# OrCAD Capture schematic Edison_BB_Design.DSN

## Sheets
1 02) Table of Contents: title: TABLE OF CONTENTS; rev: 2; note: H49905
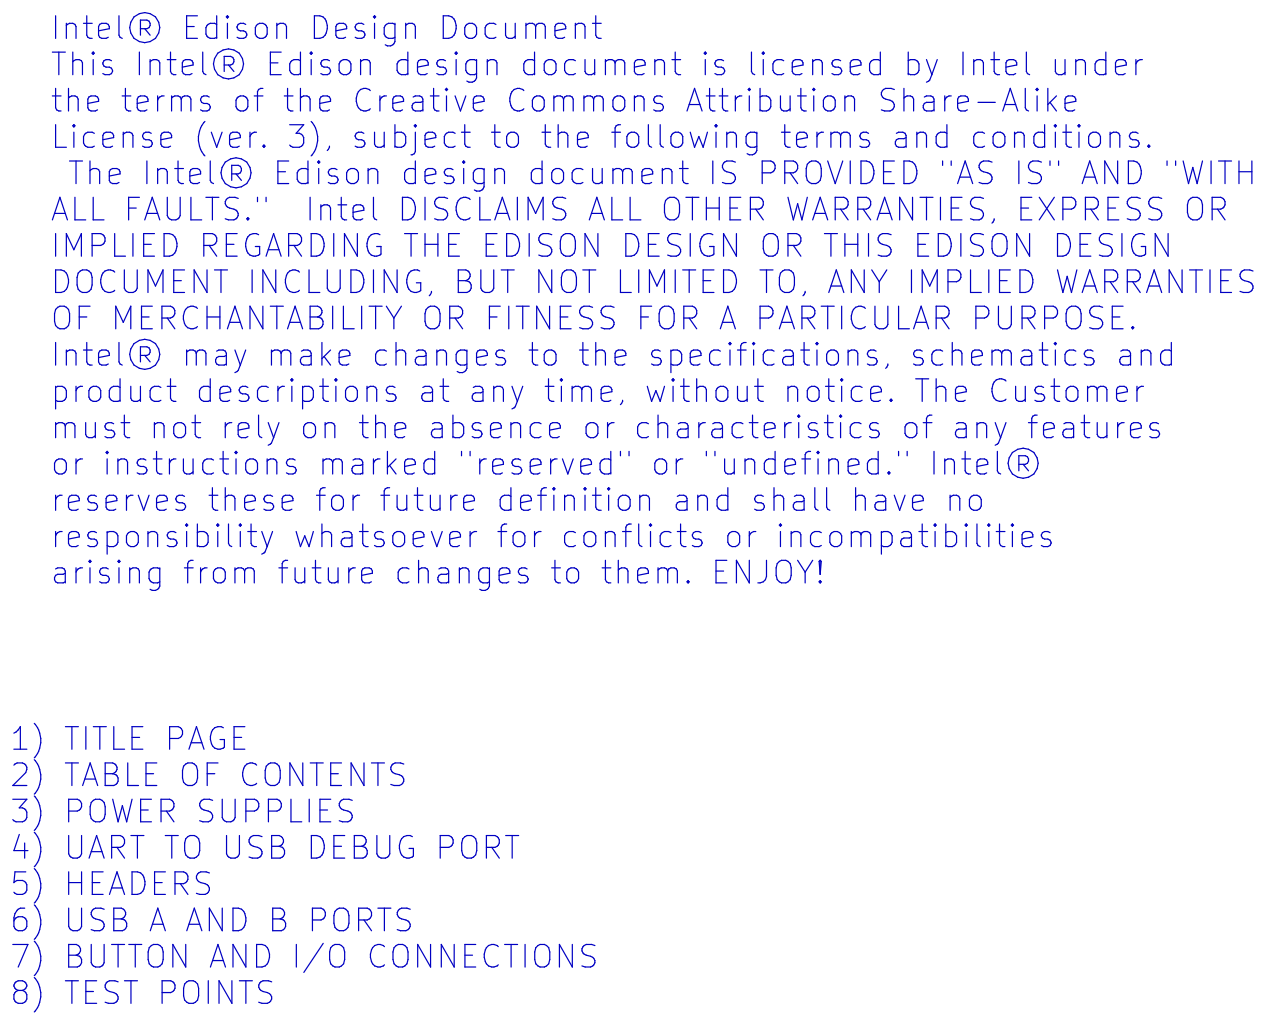
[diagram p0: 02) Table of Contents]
2 03) POWER SUPPLIES: size A; title: POWER SUPPLIES
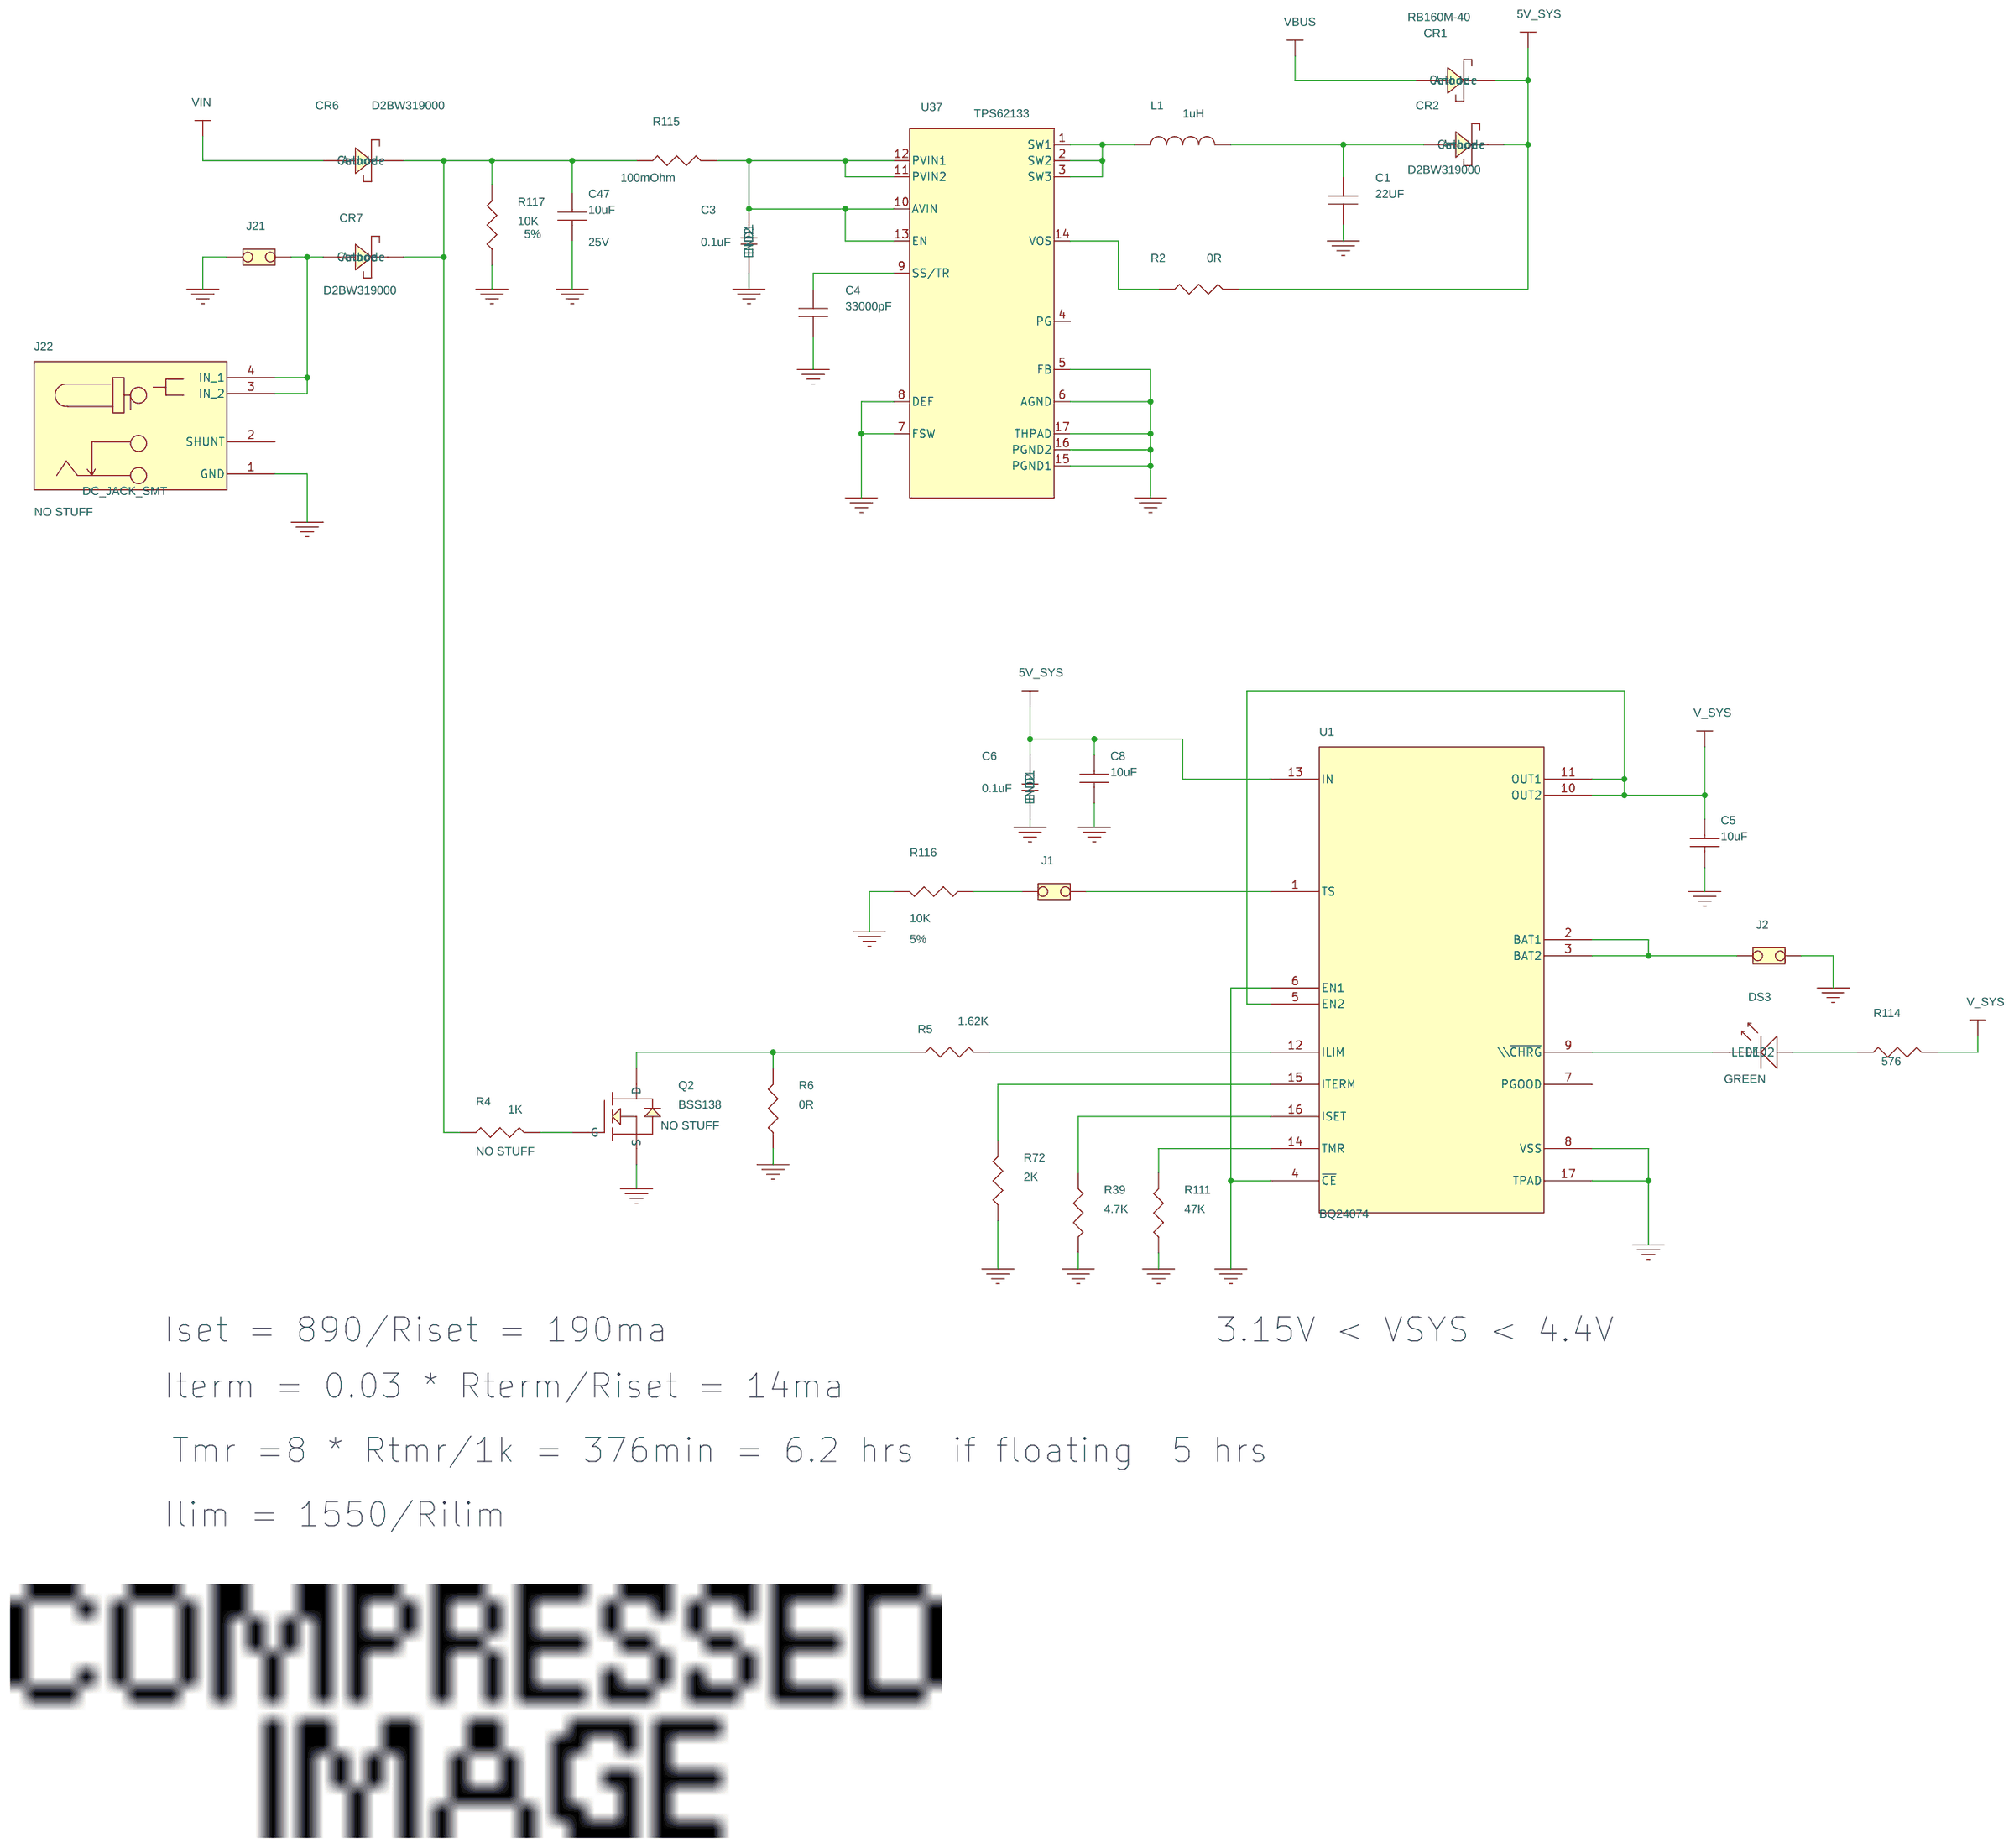
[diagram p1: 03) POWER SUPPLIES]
3 05) HEADER: size A; title: HEADERS
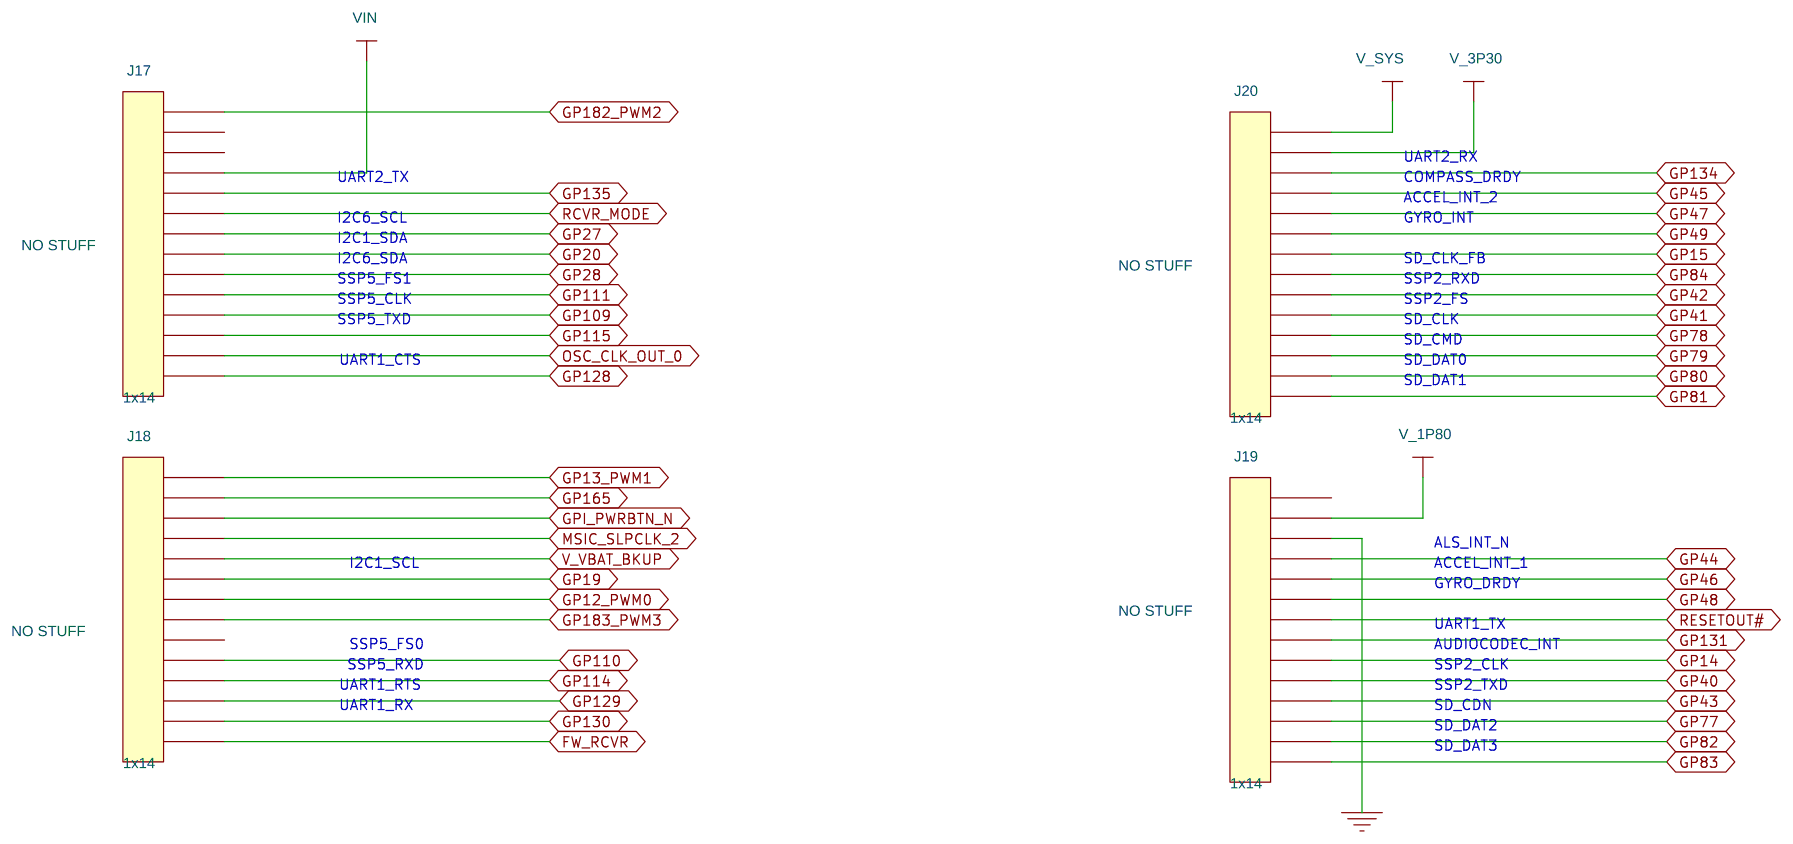
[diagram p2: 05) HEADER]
4 01) Title Page: title: Title page
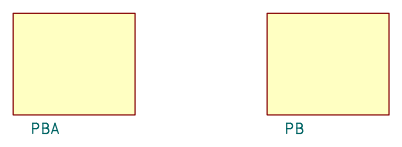
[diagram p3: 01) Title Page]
5 04) UART to USB debug port: size B; title: UART TO USB
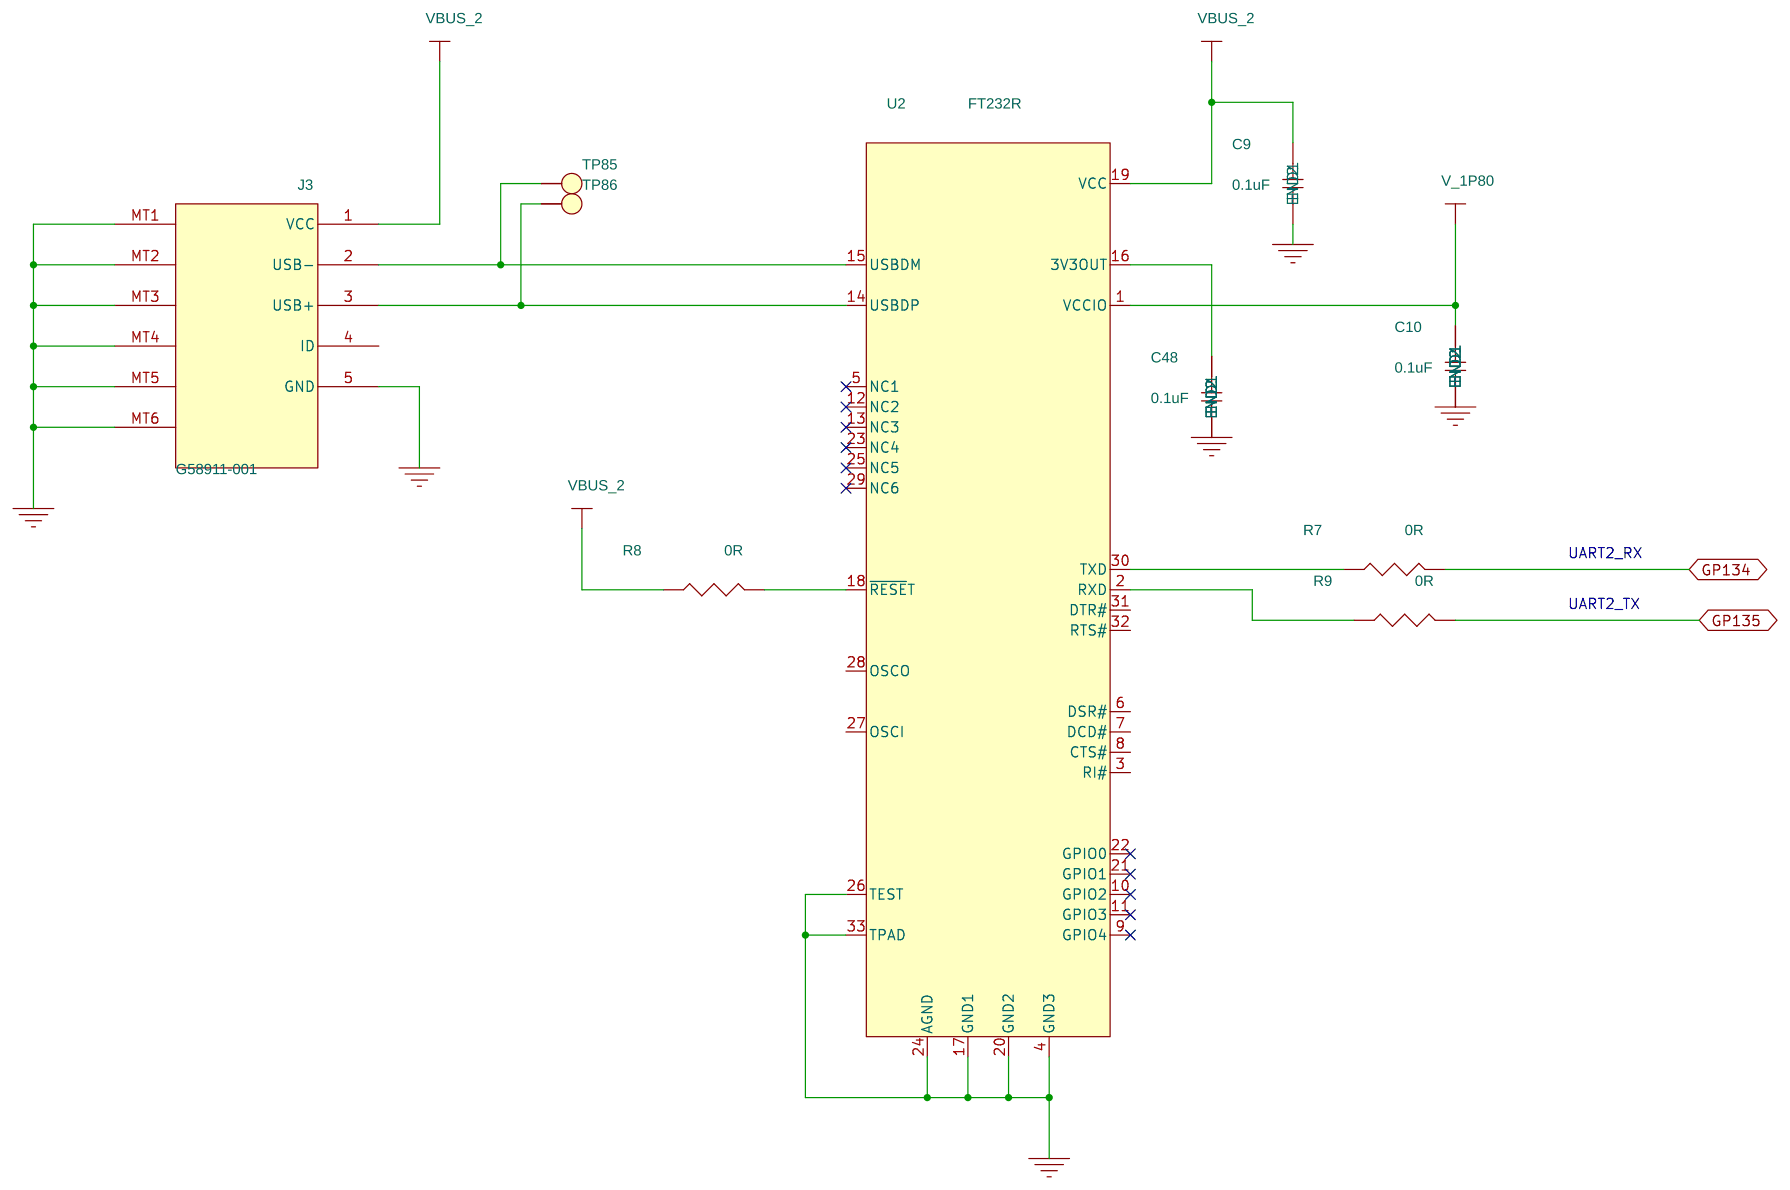
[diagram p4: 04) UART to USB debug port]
6 06) USB: size A; title: USB - OTG
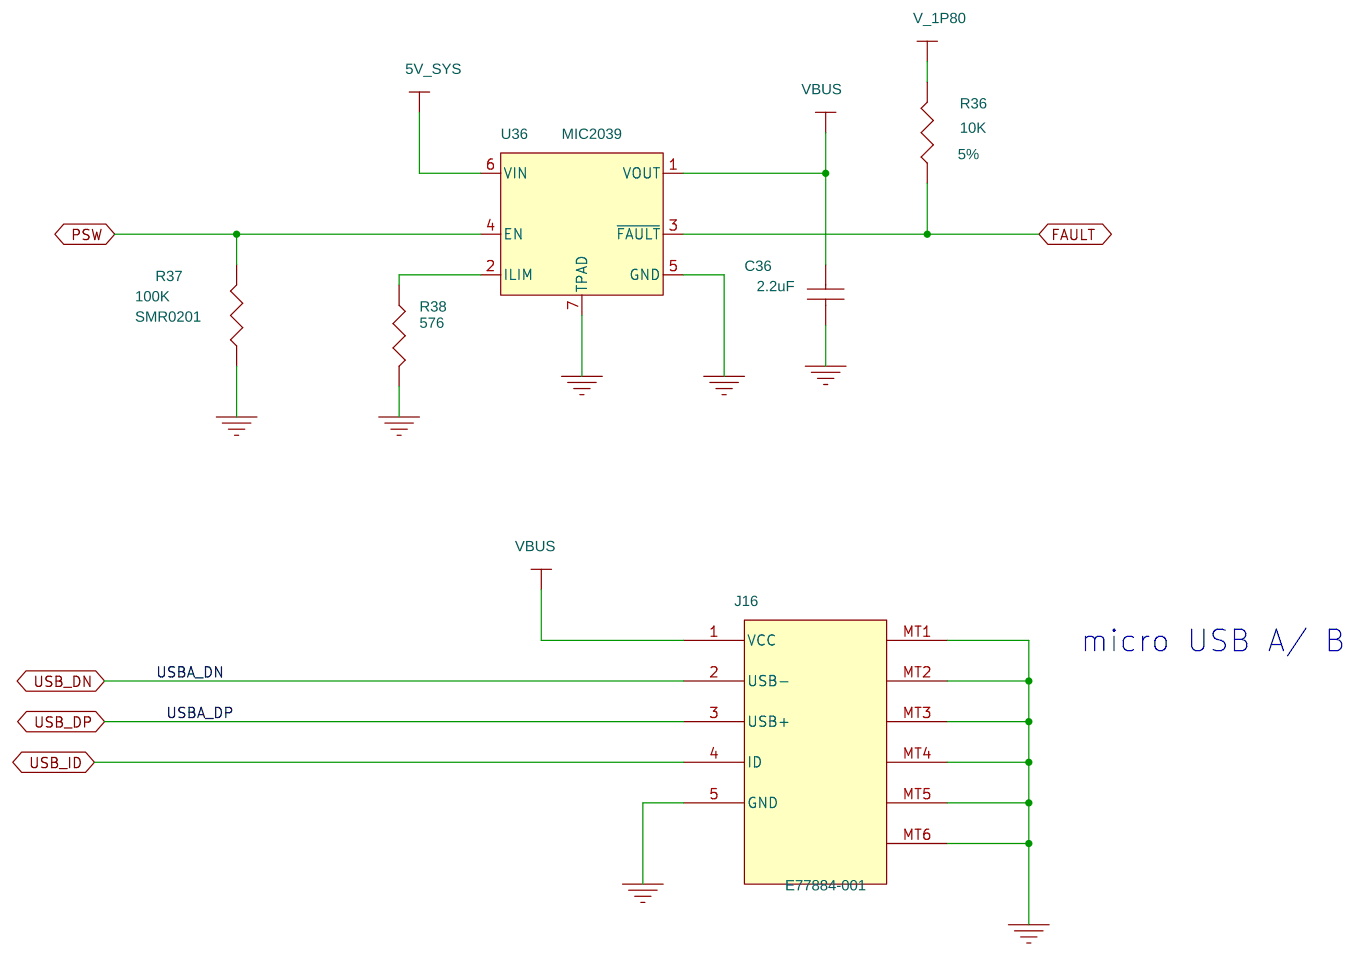
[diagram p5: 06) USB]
7 08) TEST POINTS: size A; title: TEST POINTS
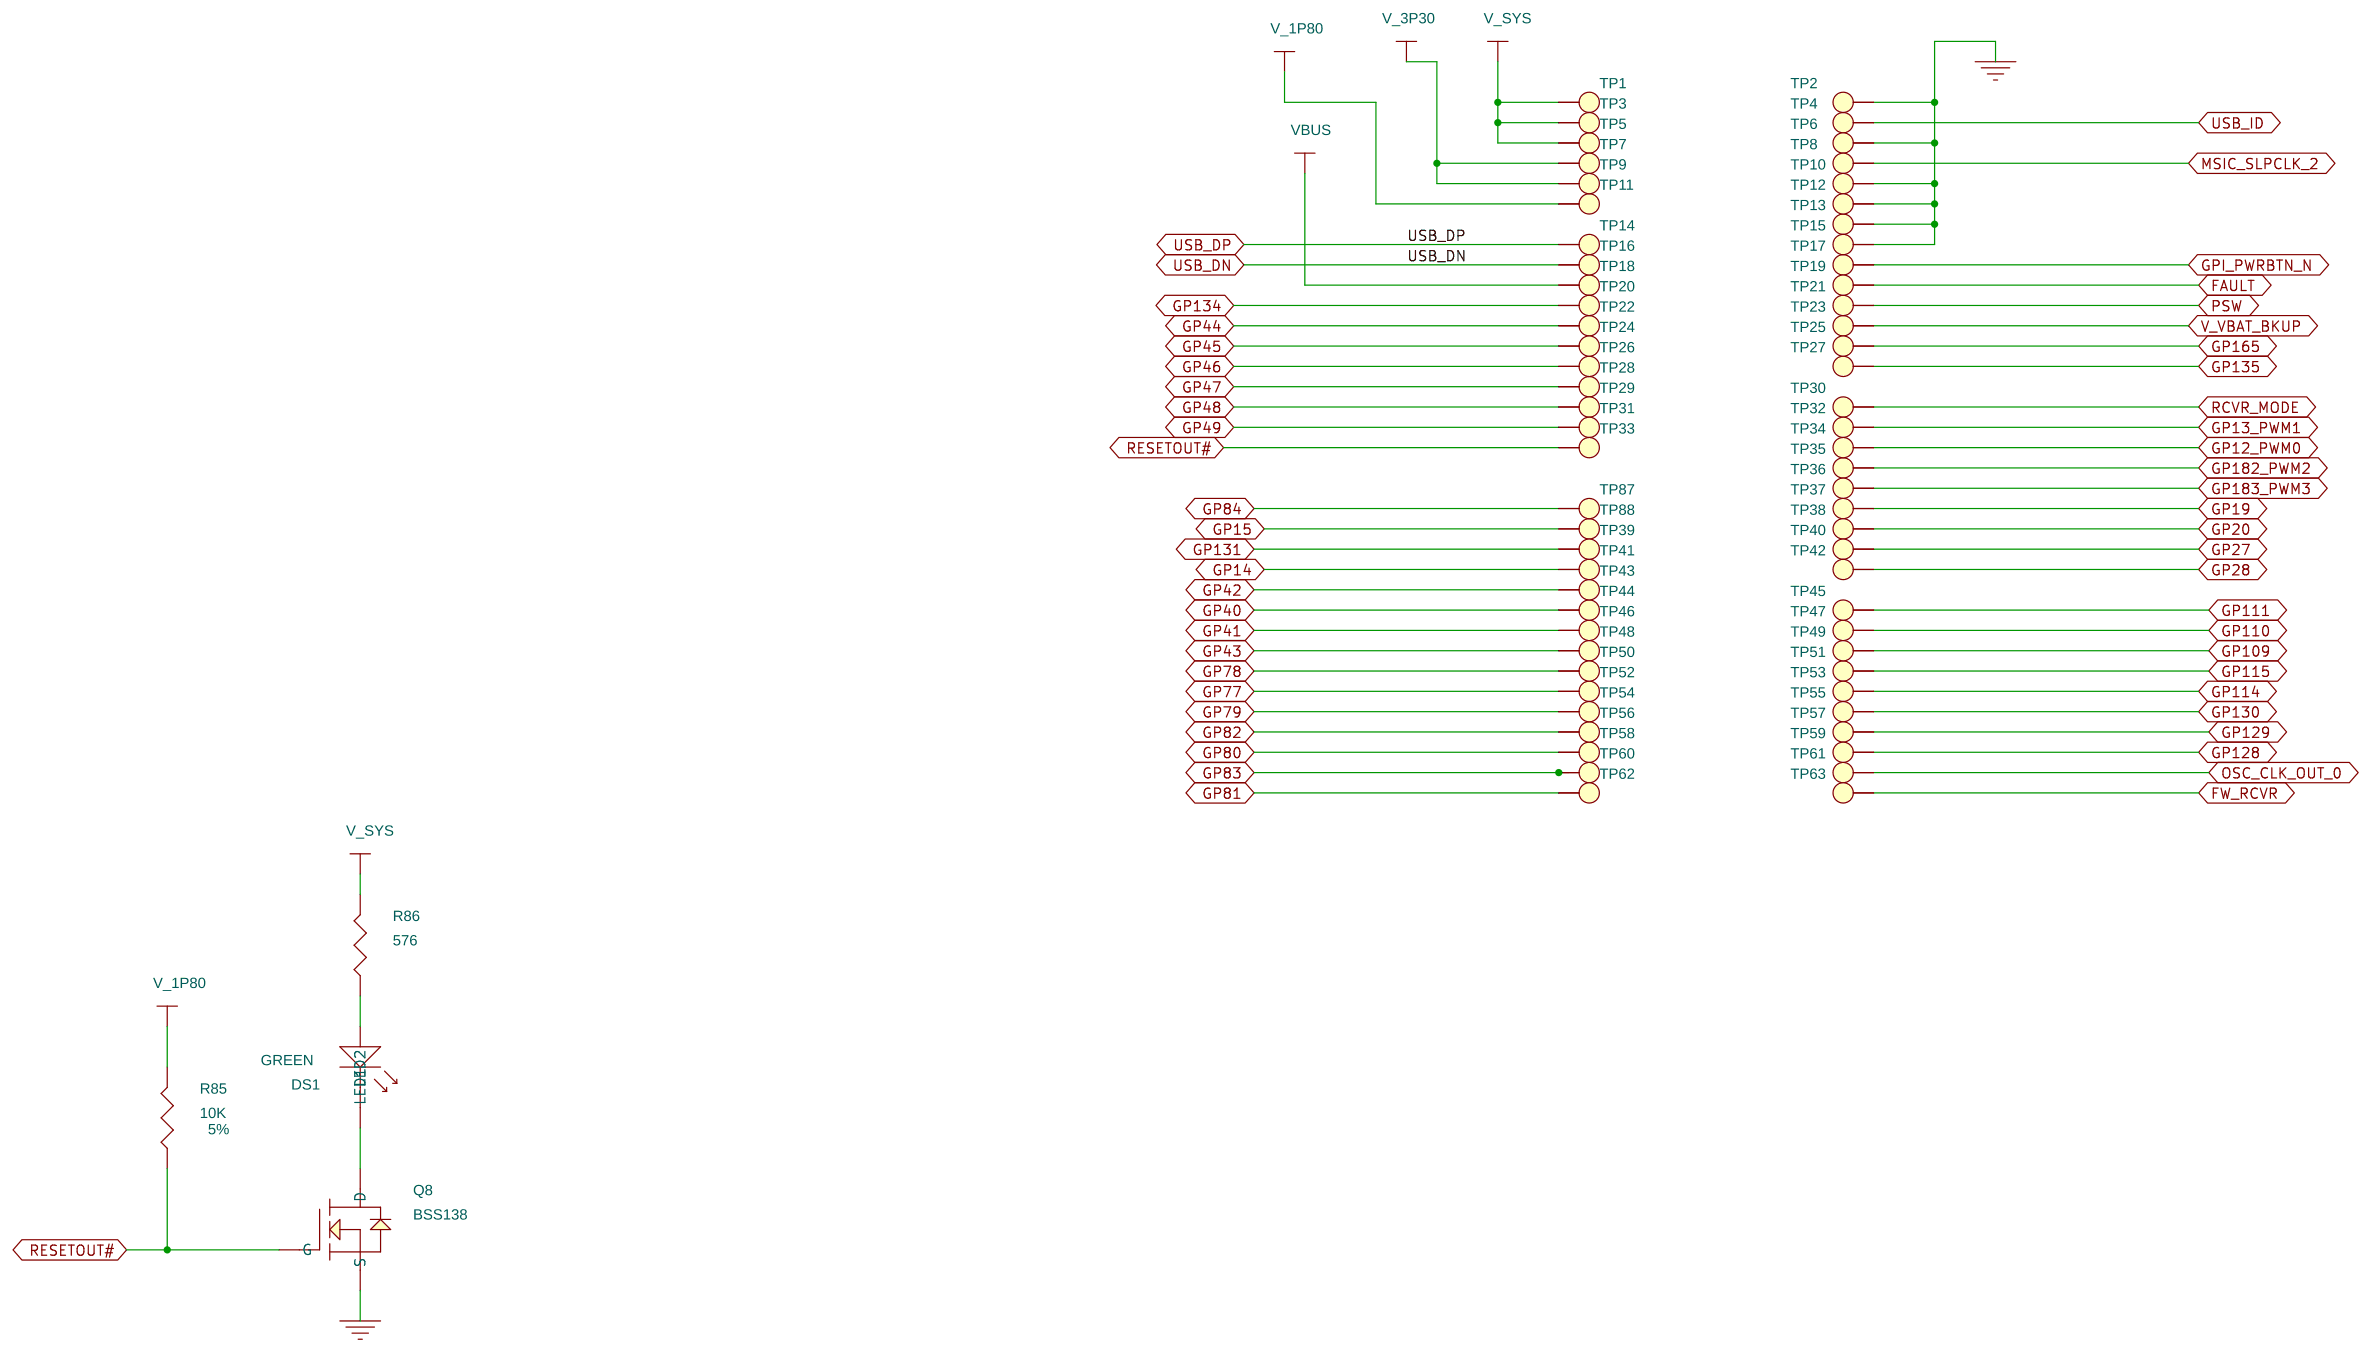
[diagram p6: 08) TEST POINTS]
8 07) Button and I/O Connections: size A; title: BUTTON AND I/O CONNECTIONS
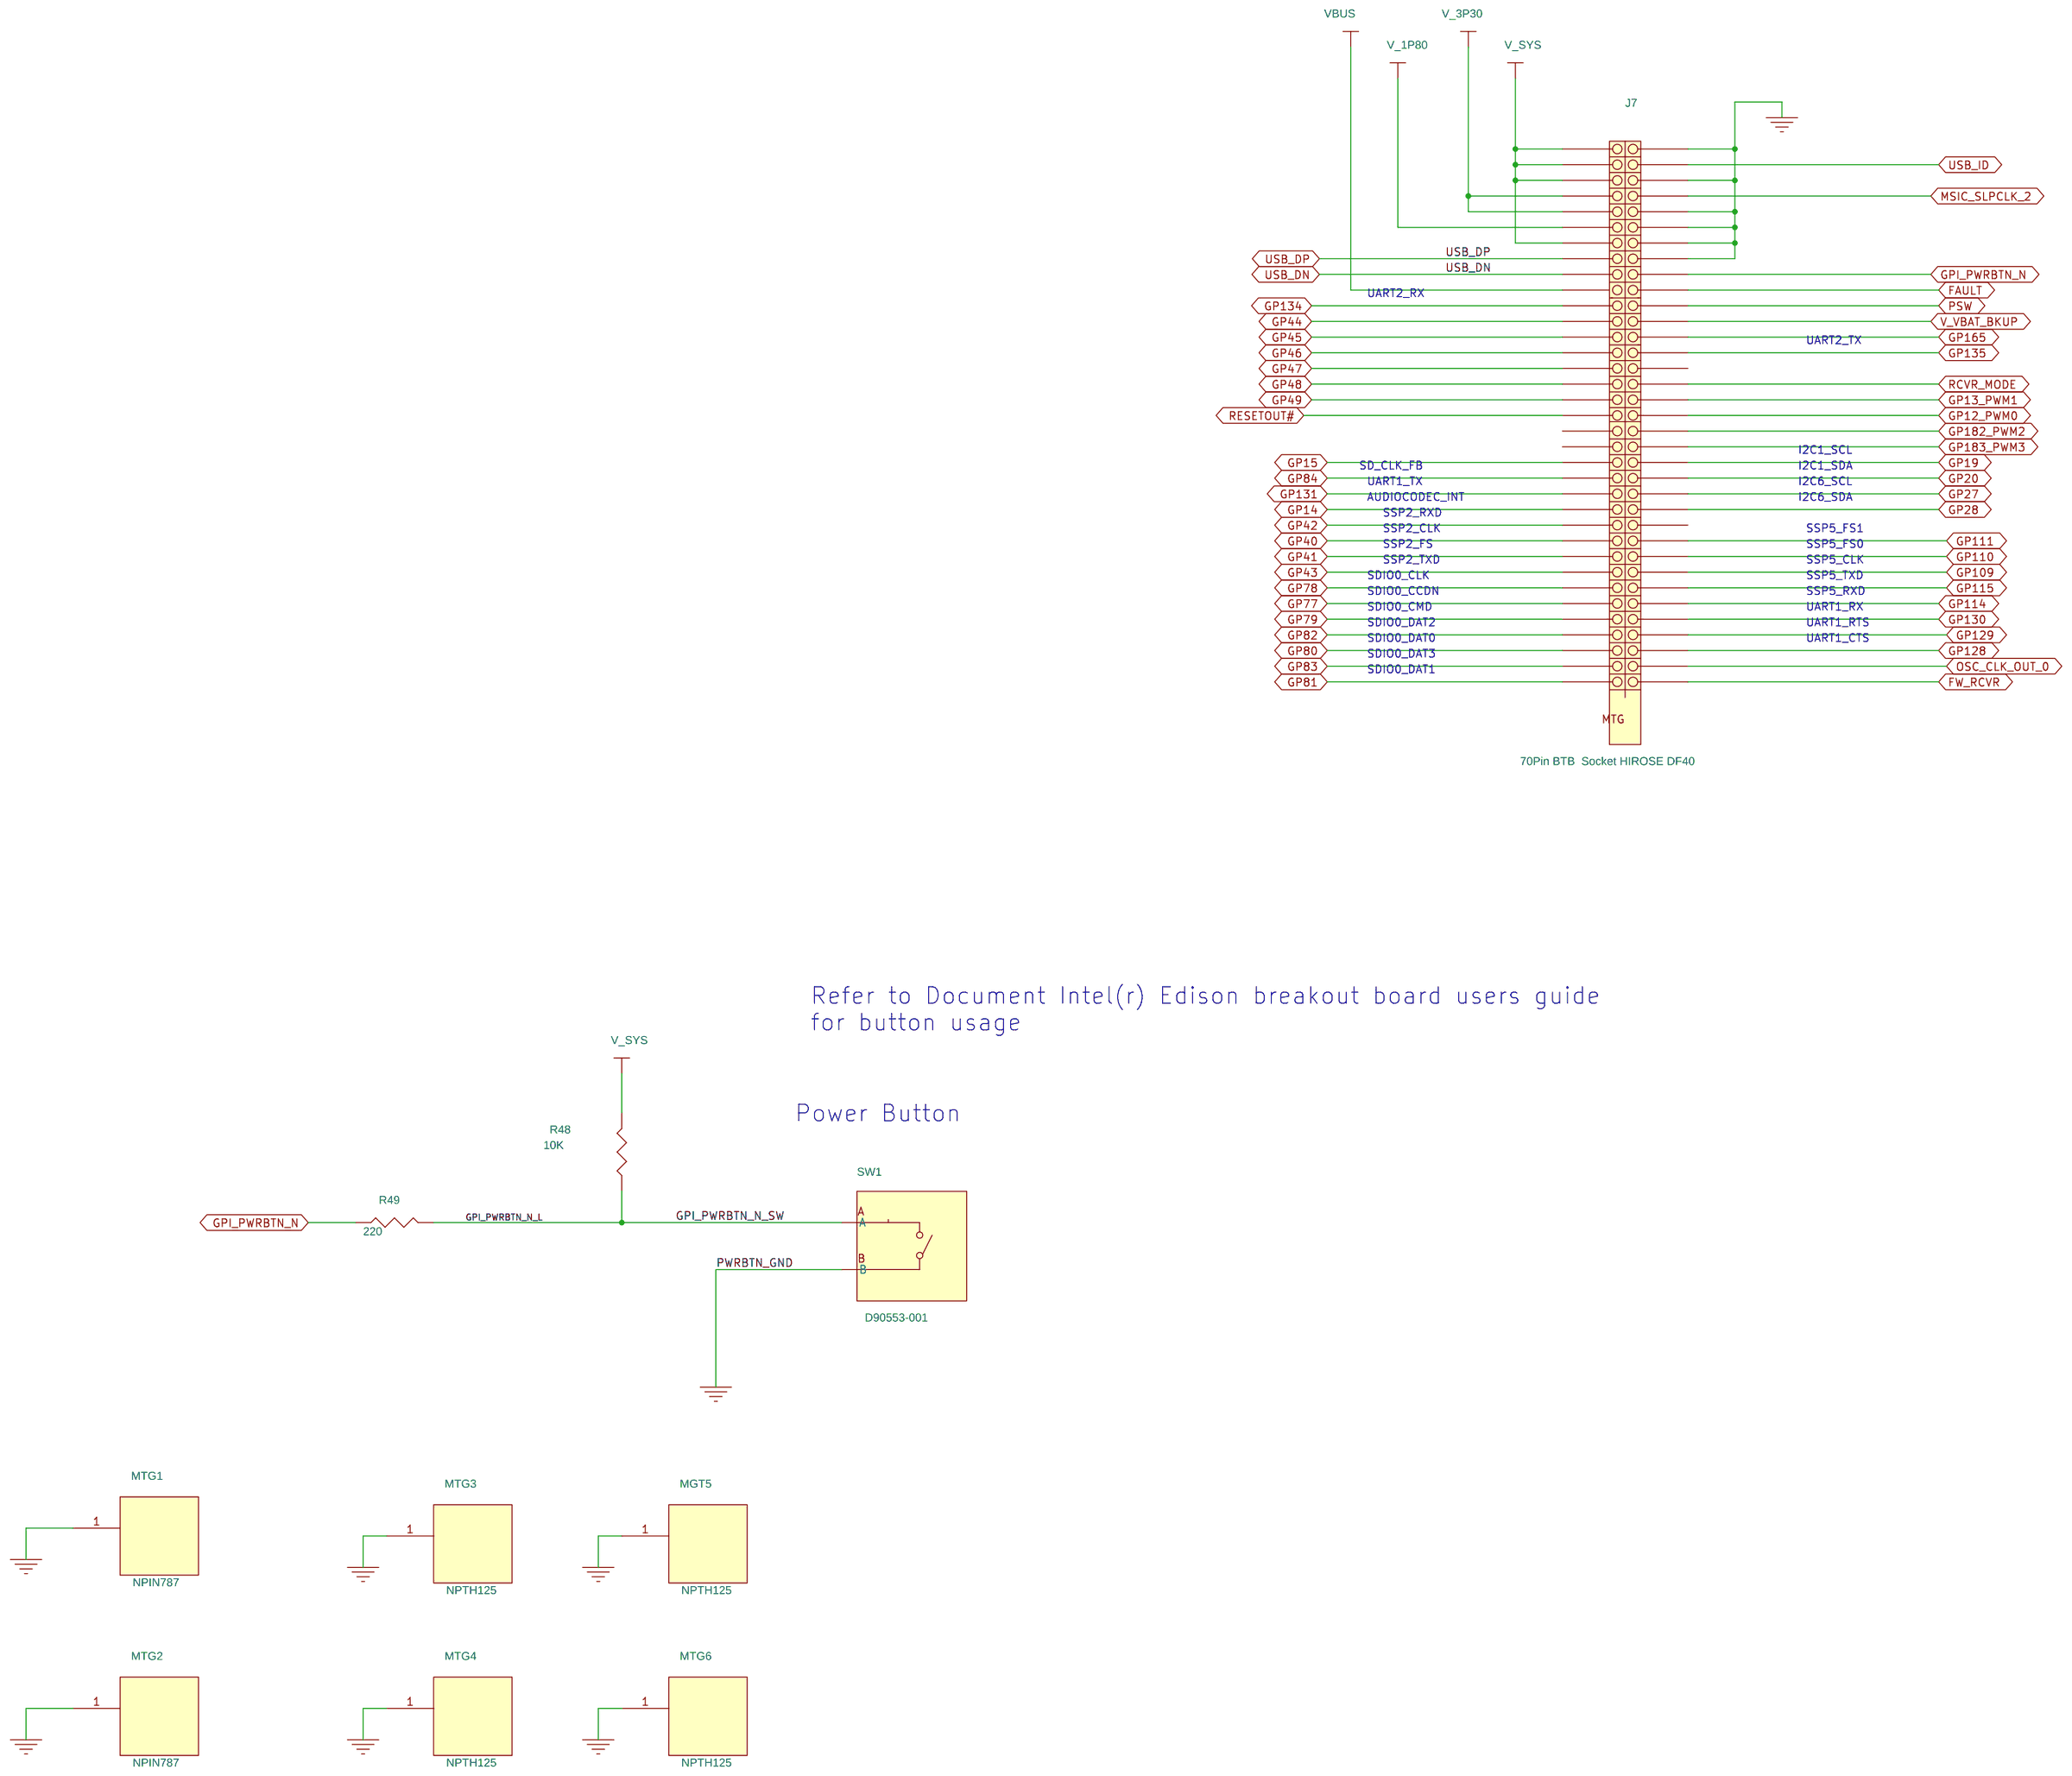
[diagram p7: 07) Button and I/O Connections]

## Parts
sheet 01) Title Page
A1  PBA
A2  PB
sheet 03) POWER SUPPLIES
C1  22UF  [SMC0603_hi_value]
C3  0.1uF  [C0201]
C4  33000pF  [SMC0201]
C5  10uF  [SMC0402]
C6  0.1uF  [C0201]
C8  10uF  [SMC0402]
C47  10uF  [SMC0805]
CR1  RB160M-40  [SOD123_67x106]
CR2  D2BW319000  [SCR_27X17MA]
CR6  D2BW319000  [SCR_27X17MA]
CR7  D2BW319000  [SCR_27X17MA]
DS3  GREEN  [smled0402]
J1  CON2_HDR  [102276-001]
J2  CON2_HDR  [102276-001]
J21  CON2_HDR  [102276-001]
J22  DC_JACK_SMT  [dc_pwr_jack_SM_14p8x9mm]
L1  1uH  [SML0805]
Q2  BSS138  [SOT23]
R2  0R  [R0201]
R4  1K  [R0201]
R5  1.62K  [R0201]
R6  0R  [R0201]
R39  4.7K  [SMR0201]
R72  2K  [SMR0201]
R111  47K  [SMR0201]
R114  576  [SMR0402]
R115  100mOhm  [SMR0402]
R116  10K  [SMR0201]
R117  10K  [SMR0201]
U1  BQ24074  [lcc16_3x3mm_ep61]
U37  TPS62133  [LCC16_3X3MM_67DIE_39H]
sheet 04) UART to USB debug port
C9  0.1uF  [C0201]
C10  0.1uF  [C0201]
C48  0.1uF  [C0201]
J3  G58911-001  [RCPT_USB_5P_DIP_SM]
R7  0R  [R0201]
R8  0R  [R0201]
R9  0R  [R0201]
TP85  30 MIL TESTPAD  [TP30S]
TP86  30 MIL TESTPAD  [TP30S]
U2  FT232R  [lcc32_p5mm_3p2sq_nonc]
sheet 05) HEADER
J17  1x14  [1x14rcpt_2p54_vt_th]
J18  1x14  [1x14rcpt_2p54_vt_th]
J19  1x14  [1x14rcpt_2p54_vt_th]
J20  1x14  [1x14rcpt_2p54_vt_th]
sheet 06) USB
C36  2.2uF  [SMC0603_hi_value]
J16  E77884-001  [RCPT_USB_5P_6MTG_SM]
R36  10K  [SMR0201]
R37  100K  [SMR0201]
R38  576  [SMR0402]
U36  MIC2039  [DFN6P_65M_2X2M]
sheet 07) Button and I/O Connections
J7  70Pin BTB  Socket HIROSE DF40  [2x35_p4mm_btb_axt_skt_mb]
MGT5  NPTH125  [SYMBOL_NPTH125]
MTG1  NPIN787  [NPIN787]
MTG2  NPIN787  [NPIN787]
MTG3  NPTH125  [SYMBOL_NPTH125]
MTG4  NPTH125  [SYMBOL_NPTH125]
MTG6  NPTH125  [SYMBOL_NPTH125]
R48  10K  [SMR0201]
R49  220  [SMR0201]
SW1  LIGHT TOUCH SWITCH EVQP7J01P  [SSW2RPB]
sheet 08) TEST POINTS
DS1  GREEN  [smled0402]
Q8  BSS138  [SOT23]
R85  10K  [SMR0201]
R86  576  [SMR0402]
TP1  30 MIL TESTPAD  [TP30S]
TP2  30 MIL TESTPAD  [TP30S]
TP3  30 MIL TESTPAD  [TP30S]
TP4  30 MIL TESTPAD  [TP30S]
TP5  30 MIL TESTPAD  [TP30S]
TP6  30 MIL TESTPAD  [TP30S]
TP7  30 MIL TESTPAD  [TP30S]
TP8  30 MIL TESTPAD  [TP30S]
TP9  30 MIL TESTPAD  [TP30S]
TP10  30 MIL TESTPAD  [TP30S]
TP11  30 MIL TESTPAD  [TP30S]
TP12  30 MIL TESTPAD  [TP30S]
TP13  30 MIL TESTPAD  [TP30S]
TP14  30 MIL TESTPAD  [TP30S]
TP15  30 MIL TESTPAD  [TP30S]
TP16  30 MIL TESTPAD  [TP30S]
TP17  30 MIL TESTPAD  [TP30S]
TP18  30 MIL TESTPAD  [TP30S]
TP19  30 MIL TESTPAD  [TP30S]
TP20  30 MIL TESTPAD  [TP30S]
TP21  30 MIL TESTPAD  [TP30S]
TP22  30 MIL TESTPAD  [TP30S]
TP23  30 MIL TESTPAD  [TP30S]
TP24  30 MIL TESTPAD  [TP30S]
TP25  30 MIL TESTPAD  [TP30S]
TP26  30 MIL TESTPAD  [TP30S]
TP27  30 MIL TESTPAD  [TP30S]
TP28  30 MIL TESTPAD  [TP30S]
TP29  30 MIL TESTPAD  [TP30S]
TP30  30 MIL TESTPAD  [TP30S]
TP31  30 MIL TESTPAD  [TP30S]
TP32  30 MIL TESTPAD  [TP30S]
TP33  30 MIL TESTPAD  [TP30S]
TP34  30 MIL TESTPAD  [TP30S]
TP35  30 MIL TESTPAD  [TP30S]
TP36  30 MIL TESTPAD  [TP30S]
TP37  30 MIL TESTPAD  [TP30S]
TP38  30 MIL TESTPAD  [TP30S]
TP39  30 MIL TESTPAD  [TP30S]
TP40  30 MIL TESTPAD  [TP30S]
TP41  30 MIL TESTPAD  [TP30S]
TP42  30 MIL TESTPAD  [TP30S]
TP43  30 MIL TESTPAD  [TP30S]
TP44  30 MIL TESTPAD  [TP30S]
TP45  30 MIL TESTPAD  [TP30S]
TP46  30 MIL TESTPAD  [TP30S]
TP47  30 MIL TESTPAD  [TP30S]
TP48  30 MIL TESTPAD  [TP30S]
TP49  30 MIL TESTPAD  [TP30S]
TP50  30 MIL TESTPAD  [TP30S]
TP51  30 MIL TESTPAD  [TP30S]
TP52  30 MIL TESTPAD  [TP30S]
TP53  30 MIL TESTPAD  [TP30S]
TP54  30 MIL TESTPAD  [TP30S]
TP55  30 MIL TESTPAD  [TP30S]
TP56  30 MIL TESTPAD  [TP30S]
TP57  30 MIL TESTPAD  [TP30S]
TP58  30 MIL TESTPAD  [TP30S]
TP59  30 MIL TESTPAD  [TP30S]
TP60  30 MIL TESTPAD  [TP30S]
TP61  30 MIL TESTPAD  [TP30S]
TP62  30 MIL TESTPAD  [TP30S]
TP63  30 MIL TESTPAD  [TP30S]
TP87  30 MIL TESTPAD  [TP30S]
TP88  30 MIL TESTPAD  [TP30S]

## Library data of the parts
A1 = PBA: PBA, EDISON MINI BREAKOUT; PART_NUMBER: H49905-200
A2 = PBA: PB, EDISON MINI BREAKOUT, 1-UP; PART_NUMBER: H49904-002
C1 = CAPC,X5R,0603,6.3V,20%,22UF: CAPC,X5R,0603,22.000UF,6.300V,+/- 20%
C3 C6 C9 C10 C48 = CAP: CAPC,X5R,0201,0.1UF,10.00V,+/- 10%; Code: 27; Manufacturer: GENERIC; PART_NUMBER: C83410-014; Process: SMD
C4 = CAPC,X5R,0201,6.3V,10%,33000pF: CAPC,X5R,0201,0.033UF,6.3V,+/- 10%
C5 C8 = CAPC,X5R,0402,6.3V,20%,10uF: CAP C,10UF,0402,X5R,6.3V,+/-20%,; PART_NUMBER: A36096-114
C47 = CAPC,X7R,0805,50V,10%,1.0uF: CAPC,X5R,0805,10.00UF,25.00V,+/- 10%; Device: G27061-002; IPN: G27061-002; PART NUMBER: G27061-002; PART_NUMBER: G27061-002; RATING: 25V
CR1 = DIO,SHTKY,SOD123,RB160M-40
CR2 CR6 CR7 = DIO,SHTKY,DB2W319000L
DS1 DS3 = LED,SMT,GREEN,V,0402: LED,1005,SM,GRN,V,1.00,RC,1; Device: E54986-003; IPN: E54986-003; PART_NUMBER: E54986-003
J1 J2 J21 = CON2,HDR,TH,0.1in,A91829-020: CONN,HDR,1 X 2,PLG,VT,0.1,093ST,KP; Device: E81838-001; IPN: E81838-001; PART_NUMBER: E81838-001
J22 = CON3,Pwr-Jack,SMT,KLDX-2mm: NO_STUFF: NO STUFF
L1 = INDCT,1uH,1.1A,30%,0805: INDCT,MTILAYER,1.00uH,1.1A,0805,30.0%,
Q2 = XSTR,BSS138,FET,NCH,SOT23: IC,DS,FET N,SOT-23,BSS138LT3G; NO_STUFF: NO STUFF
R2 R6-R9 = R_0: RES_D,0201,0.00OHM,1/20W; Manufacturer: Yageo; PART_NUMBER: C80792-009
R4 = R0603: RES_D,0201,1.00kOHM,1.00%,1/20W; Manufacturer: Yageo; NO STUFF: NO STUFF; PART_NUMBER: C48657-010; Part Type: Resister
R5 = R0603: RES_D,0201,1.62kOHM,1.00%,1/20W; Manufacturer: Yageo; PART_NUMBER: C48657-075; Part Type: Resister
R39 = RESD,0201,5%,1_20W,4.7K: RES D,0201,4.70 kOHM,5.00%,1/20W,YES; ROOM: APE_PMIC_MISC
R72 = RESD,0201,1%,1_20W,2K: RES D,0201,2.00 kOHM,1.00%,1/20W,YES; ROOM: APE_PMIC_MISC
R111 = RESD,0201,1%,1_20W,47K: RES_D,0201,47.0kOHM,1.00%,1/20W,
R38 R86 R114 = RESD,0201,1%,1_20W,562: RES D,0402,576.00 OHM,1.00%,1/16W,YES; PART_NUMBER: A93548-403
R115 = RESD,0402,1%,1_16W,100mOhm: RES D,0402,0.10 OHM,1.00%,,1/16W; Device: C65288-008; IPN: C65288-008; PART_NUMBER: C65288-008
R36 R85 R116 R117 = RESD,0201,5%,1_20W,10K: RES D,0201,10.00 kOHM,5.00%,1/20W,YES; PART_NUMBER: C80792-002; ROOM: AUDIO_CODEC; TOL: 5%
U1 = IC,BQ24232,QFN16,USB_CHGR: PART_NUMBER: H52571-001
U37 = TPS62133_0: IC,LIN,QFN,TPS62133,CONTROLR; PART NUMBER: H31879-001; Part_Number: H31879-001
J3 = CON4,USB,RA,_1: CONN,MISC,5P,MICRO USB,B TYPE,RECEPT,2013499-1
TP1-TP63 TP85-TP88 = TestPad,C80,SMT: DEVICE: TESTPAD_30; PART_NUMBER: TESTPAD_30; ROOM: TEST_APE
U2 = FT232R_0: IC,VLSI,OTHER,FT232,QFN,32; MFG PN: FT232RQ-REEL; PART_NUMBER: H40970-001
J17-J20 = CON14,1X14,0.1,0.093: NO_STUFF: NO STUFF
C36 = CAPC,X5R,0603,25V,10%,2.2uF: CAPC,X5R,0603,2.2UF,25.00V,+/- 10%; ROOM: USB
J16 = CON4,USB,RA,_1: CONN,MISC,5P,MICRO USB,AB TYPE,RECEPT,2013499-1
R37 = RESD,0201,5%,1_20W,100K: RES D,0201,100.00 kOHM,5.00%,1/20W,YES; ROOM: APE_PMIC_MISC
U36 = IC,MIC2039,UsbPwrSwtch_0: IC,LIN,ANALOGSWITCH,DFN,MIC2039,; PART_NUMBER: H40907-001
J7 = CON70,SKT,SM,4mm,AXT570124_0: CONN,MISC,70P,BTB SKT,.4MM SMT; DEVICE: H42241-001; IPN: H42241-001; MFG: HIROSE; PART_NUMBER: H49811-001
MGT5 MTG3 MTG4 MTG6 = symbol_npth125_0
MTG1 MTG2 = MOUNTING_HOLE_787
R48 = RESD,0201,5%,1_20W,10K: RES D,0201,10.00 kOHM,5.00%,1/20W,YES; ROOM: USB
R49 = RESD,0201,5%,1_20W,220: RES_D,0201,220.00OHM,5.00%,1/20W,; ROOM: UI_BUTTONS
SW1 = SWITCH,EVQP7J01P,4P,PWR_0: CONN,SWIT,TACTILE,VT,SPST,2,50.0 mA,SMT>; DEVICE: D90553-001; IPN: D90553-001; PART_NUMBER: D90553-001; ROOM: UI_BUTTONS
Q8 = XSTR,BSS138,FET,NCH,SOT23: IC,DS,FET N,SOT-23,BSS138LT3G

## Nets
5V_SYS: C6.2(END2) C8.1 CR1.1(Cathode) CR2.1(Cathode) R2.2 U1.13(IN) U36.6(VIN)
GND: C1.2 C3.1(END1) C4.2 C5.2 C6.1(END1) C8.2 C9.1(END1) C10.1(END1) C36.2 C47.2 C48.1(END1) J2.2 J3.5(GND) J3.MT1 J3.MT2 J3.MT3 J3.MT4 J3.MT5 J3.MT6 J7.1 J7.5 J7.9 J7.11 J7.13 J7.15 J16.5(GND) J16.MT1 J16.MT2 J16.MT3 J16.MT4 J16.MT5 J16.MT6 J19.3 J21.1 J22.1(GND) MGT5.1 MTG1.1 MTG2.1 MTG3.1 MTG4.1 MTG6.1 Q2.2(S) Q8.2(S) R6.1 R37.2 R38.2 R39.1 R72.1 R111.1 R116.2 R117.1 SW1.2(B) TP2.1 TP6.1 TP10.1 TP12.1 TP13.1 TP15.1 U1.4(~{CE}) U1.6(EN1) U1.8(VSS) U1.17(TPAD) U2.4(GND3) U2.17(GND1) U2.20(GND2) U2.24(AGND) U2.26(TEST) U2.33(TPAD) U36.5(GND) U36.7(TPAD) U37.5(FB) U37.6(AGND) U37.7(FSW) U37.8(DEF) U37.15(PGND1) U37.16(PGND2) U37.17(THPAD)
VBUS: C36.1 CR1.2(Anode) J7.20 J16.1(VCC) TP18.1 U36.1(VOUT)
VBUS_2: C9.2(END2) J3.1(VCC) R8.1 U2.19(VCC)
VIN: CR6.2(Anode) J17.4
FAULT: J7.19 R36.1 TP19.1 U36.3(~{FAULT})
FW_RCVR: J7.69 J18.14 TP63.1
GP12_PWM0: J7.35 J18.7 TP34.1
GP13_PWM1: J7.33 J18.1 TP32.1
GP14: J7.48 J19.9 TP41.1
GP15: J7.42 J20.7 TP88.1
GP19: J7.41 J18.6 TP37.1
GP20: J7.43 J17.8 TP38.1
GP27: J7.45 J17.7 TP40.1
GP28: J7.47 J17.9 TP42.1
GP40: J7.52 J19.10 TP44.1
GP41: J7.54 J20.10 TP46.1
GP42: J7.50 J20.9 TP43.1
GP43: J7.56 J19.11 TP48.1
GP44: J7.24 J19.4 TP22.1
GP45: J7.26 J20.4 TP24.1
GP46: J7.28 J19.5 TP26.1
GP47: J7.30 J20.5 TP28.1
GP48: J7.32 J19.6 TP29.1
GP49: J7.34 J20.6 TP31.1
GP77: J7.60 J19.12 TP52.1
GP78: J7.58 J20.11 TP50.1
GP79: J7.62 J20.12 TP54.1
GP80: J7.66 J20.13 TP58.1
GP81: J7.70 J20.14 TP62.1
GP82: J7.64 J19.13 TP56.1
GP83: J7.68 J19.14 TP60.1
GP84: J7.44 J20.8 TP87.1
GP109: J7.55 J17.11 TP49.1
GP110: J7.53 J18.10 TP47.1
GP111: J7.51 J17.10 TP45.1
GP114: J7.59 J18.11 TP53.1
GP115: J7.57 J17.12 TP51.1
GP128: J7.65 J17.14 TP59.1
GP129: J7.63 J18.12 TP57.1
GP130: J7.61 J18.13 TP55.1
GP131: J7.46 J19.8 TP39.1
GP134: J7.22 J20.3 R7.2 TP20.1
GP135: J7.27 J17.5 R9.2 TP27.1
GP165: J7.25 J18.2 TP25.1
GP182_PWM2: J7.37 J17.1 TP35.1
GP183_PWM3: J7.39 J18.8 TP36.1
GPI_PWRBTN_N: J7.17 J18.3 R49.1 TP17.1
GPI_PWRBTN_N_L: R48.2 R49.2 SW1.1(A)
MSIC_SLPCLK_2: J7.7 J18.4 TP8.1
OSC_CLK_OUT_0: J7.67 J17.13 TP61.1
PSW: J7.21 R37.1 TP21.1 U36.4(EN)
RCVR_MODE: J7.31 J17.6 TP30.1
RESETOUT#: J7.36 J19.7 Q8.1(G) R85.1 TP33.1
USB_DN: J7.18 J16.2(USB-) TP16.1
USB_DP: J7.16 J16.3(USB+) TP14.1
USB_ID: J7.3 J16.4(ID) TP4.1
V_1P80: C10.2(END2) J7.12 J19.2 R36.2 R85.2 TP11.1 U2.1(VCCIO)
V_3P30: J7.8 J7.10 J20.2 TP7.1 TP9.1
V_SYS: C5.1 J7.2 J7.4 J7.6 J7.14 J20.1 R48.1 R86.2 R114.2 TP1.1 TP3.1 TP5.1 U1.5(EN2) U1.10(OUT2) U1.11(OUT1)
V_VBAT_BKUP: J7.23 J18.5 TP23.1
N11374: J3.2(USB-) TP85.1 U2.15(USBDM)
N11378: J3.3(USB+) TP86.1 U2.14(USBDP)
N30036849: R8.2 U2.18(~{RESE}T)
N30112835: R38.1 U36.2(ILIM)
N30125838: R7.1 U2.30(TXD)
N30125857: R9.1 U2.2(RXD)
N30202561: DS1.1(LED1) Q8.3(D)
N30202678: DS1.2(LED2) R86.1
N30230113: C48.2(END2) U2.16(3V3OUT)
N30332540: C47.1 CR6.1(Cathode) CR7.1(Cathode) R4.1 R115.1 R117.2
N30332593: CR7.2(Anode) J21.2 J22.3(IN_2) J22.4(IN_1)
N30352182: J2.1 U1.2(BAT1) U1.3(BAT2)
N30352285: DS3.1(LED1) U1.9(\\~{CHRG})
N30352331: DS3.2(LED2) R114.1
N30352588: J1.2 U1.1(TS)
N30354262: R39.2 U1.16(ISET)
N30354335: R72.2 U1.15(ITERM)
N30354821: R111.2 U1.14(TMR)
N30354968: Q2.3(D) R5.1 R6.2
N30354976: Q2.1(G) R4.2
N30355044: R5.2 U1.12(ILIM)
N30364668: J1.1 R116.1
N30367578: C3.2(END2) R115.2 U37.10(AVIN) U37.11(PVIN2) U37.12(PVIN1) U37.13(EN)
N30367602: C4.1 U37.9(SS/TR)
N30367634: L1.1 U37.1(SW1) U37.2(SW2) U37.3(SW3)
N30367646: C1.1 CR2.2(Anode) L1.2
N30367678: R2.1 U37.14(VOS)

Not connected (* = marked no-connect by the designer): J3 4(ID); J7 29 38 40 49; J17 2 3; J18 9; J19 1; J22 2(SHUNT); U1 7(PGOOD); U2 3(RI#) 5(NC1)* 6(DSR#) 7(DCD#) 8(CTS#) 9(GPIO4)* 10(GPIO2)* 11(GPIO3)* 12(NC2)* 13(NC3)* 21(GPIO1)* 22(GPIO0)* 23(NC4)* 25(NC5)* 27(OSCI) 28(OSCO) 29(NC6)* 31(DTR#) 32(RTS#); U37 4(PG)

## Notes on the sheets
sheet 1
- Intel® Edison Design Document
  This Intel® Edison design document is licensed by Intel under
  the terms of the Creative Commons Attribution Share-Alike
  License (ver. 3), subject to the following terms and conditions.
   The Intel® Edison design document IS PROVIDED "AS IS" AND "WITH
  ALL FAULTS."  Intel DISCLAIMS ALL OTHER WARRANTIES, EXPRESS OR
  IMPLIED REGARDING THE EDISON DESIGN OR THIS EDISON DESIGN
  DOCUMENT INCLUDING, BUT NOT LIMITED TO, ANY IMPLIED WARRANTIES
  OF MERCHANTABILITY OR FITNESS FOR A PARTICULAR PURPOSE.
  Intel® may make changes to the specifications, schematics and
  product descriptions at any time, without notice. The Customer
  must not rely on the absence or characteristics of any features
  or instructions marked "reserved" or "undefined." Intel®
  reserves these for future definition and shall have no
  responsibility whatsoever for conflicts or incompatibilities
  arising from future changes to them. ENJOY!
- 1) TITLE PAGE
  2) TABLE OF CONTENTS
  3) POWER SUPPLIES
  4) UART TO USB DEBUG PORT
  5) HEADERS
  6) USB A AND B PORTS
  7) BUTTON AND I/O CONNECTIONS
  8) TEST POINTS
sheet 2
- Iset = 890/Riset = 190ma
- 3.15V < VSYS < 4.4V
- Iterm = 0.03 * Rterm/Riset = 14ma
- Tmr =8 * Rtmr/1k = 376min = 6.2 hrs  if floating  5 hrs
- Ilim = 1550/Rilim
sheet 3
- UART2_RX
- UART2_TX
- COMPASS_DRDY
- ACCEL_INT_2
- I2C6_SCL
- GYRO_INT
- I2C1_SDA
- I2C6_SDA
- SD_CLK_FB
- SSP5_FS1
- SSP2_RXD
- SSP5_CLK
- SSP2_FS
- SSP5_TXD
- SD_CLK
- SD_CMD
- UART1_CTS
- SD_DAT0
- SD_DAT1
- ALS_INT_N
- I2C1_SCL
- ACCEL_INT_1
- GYRO_DRDY
- UART1_TX
- SSP5_RXD
- SSP5_FS0
- AUDIOCODEC_INT
- SSP2_CLK
- UART1_RTS
- SSP2_TXD
- UART1_RX
- SD_CDN
- SD_DAT2
- SD_DAT3
sheet 5
- UART2_RX
- UART2_TX
sheet 6
- micro USB A/ B
sheet 8
- UART2_RX
- UART2_TX
- I2C1_SCL
- SD_CLK_FB
- I2C1_SDA
- UART1_TX
- I2C6_SCL
- AUDIOCODEC_INT
- SSP2_RXD
- I2C6_SDA
- SSP2_CLK
- SSP5_FS1
- SSP2_FS
- SSP5_FS0
- SSP2_TXD
- SSP5_CLK
- SDIO0_CLK
- SSP5_TXD
- SDIO0_CCDN
- SSP5_RXD
- SDIO0_CMD
- SDIO0_DAT2
- UART1_RTS
- UART1_RX
- SDIO0_DAT0
- UART1_CTS
- SDIO0_DAT3
- SDIO0_DAT1
- Refer to Document Intel(r) Edison breakout board users guide
  for button usage
- Power Button
